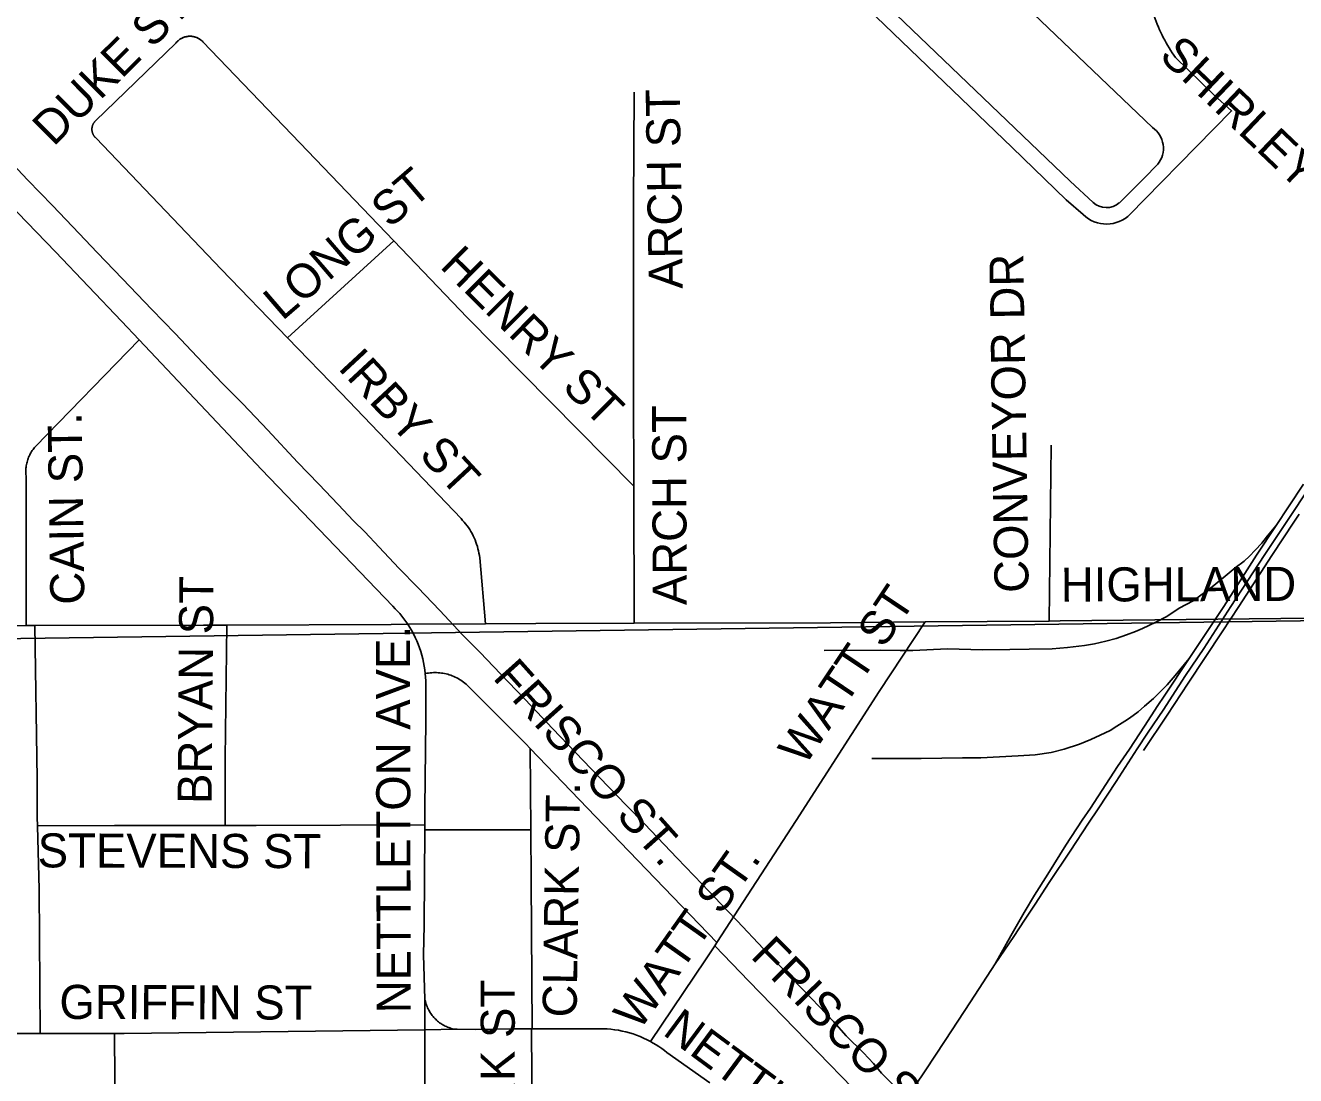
# Model space of a CAD drawing. Extents: x 1670563 to 1761545, y 515755 to 578944.
# Drawn here: x 1711003 to 1713800, y 543230 to 545541 of the extents above; entities that cross this region are included whole.
import ezdxf

# ---------------------------------------------------------------- set-up
doc = ezdxf.new("R2010")
doc.units = 0
for name, color, linetype in [('5_sectionlines', 7, 'Continuous'), ('AIRPORT', 7, 'Continuous'), ('RR Tracks', 7, 'Continuous'), ('STREETCL', 7, 'Continuous'), ('STRNAMES', 7, 'Continuous')]:
    doc.layers.add(name, color=color, linetype=linetype)

# ---------------------------------------------------------------- blocks, each defined once
blk = doc.blocks.new('RR TRACKS02')
at = {"layer": 'RR Tracks'}
for p, q in [((1710951.3, 545261.6), (1711008.8, 545200.8)), ((1711008.8, 545200.8), (1711062.7, 545145)), ((1711062.7, 545145), (1711121.5, 545083.4)), ((1711121.5, 545083.4), (1711161.2, 545041.8)), ((1711161.2, 545041.8), (1711216.9, 544983.9)), ((1711216.9, 544983.9), (1711281.6, 544916.4)), ((1711281.6, 544916.4), (1711332.7, 544863.4)), ((1711332.7, 544863.4), (1711381.4, 544811.8)), ((1711381.4, 544811.8), (1711436.9, 544753.8)), ((1711436.9, 544753.8), (1711482, 544708.1)), ((1711482, 544708.1), (1711537.4, 544650.1)), ((1711537.4, 544650.1), (1711602.6, 544579.8)), ((1711602.6, 544579.8), (1711649.4, 544531.7)), ((1713790.7, 544464.8), (1713852.9, 544558.2)), ((1711649.4, 544531.7), (1711692, 544486.9)), ((1713784.2, 544481.7), (1713817.6, 544531.4)), ((1711692, 544486.9), (1711725.8, 544451)), ((1713757, 544440.9), (1713784.2, 544481.7)), ((1711725.8, 544451), (1711750.4, 544426.4)), ((1713730.8, 544374.5), (1713790.7, 544464.8)), ((1713747.8, 544374.2), (1713797.7, 544450.3)), ((1713797.7, 544450.3), (1713807.7, 544465.7)), ((1711750.4, 544426.4), (1711782.1, 544392.5)), ((1713713.8, 544375.2), (1713757, 544440.9)), ((1713737.8, 544417.9), (1713725.9, 544401.5)), ((1713757, 544440.9), (1713737.8, 544417.9)), ((1711782.1, 544392.5), (1711825.6, 544346.5)), ((1713725.9, 544401.5), (1713711.1, 544386.1)), ((1713641.6, 544262.2), (1713713.8, 544375.2)), ((1713657.6, 544261.9), (1713730.8, 544374.5)), ((1713687, 544362.3), (1713667.1, 544347.2)), ((1713674.6, 544262.5), (1713747.8, 544374.2)), ((1713698.6, 544372.7), (1713687, 544362.3)), ((1713711.1, 544386.1), (1713698.6, 544372.7)), ((1711825.6, 544346.5), (1711867.6, 544304)), ((1713667.1, 544347.2), (1713644.9, 544328.8)), ((1713644.9, 544328.8), (1713616.2, 544305.2)), ((1711867.6, 544304), (1711915.9, 544253.6)), ((1713616.2, 544305.2), (1713574.3, 544274.7)), ((1711915.9, 544253.6), (1711966.7, 544199.1)), ((1713543.8, 544258.3), (1713516.5, 544239.9)), ((1713574.3, 544274.7), (1713543.8, 544258.3)), ((1713565.4, 544148), (1713641.6, 544262.2)), ((1713597.9, 544170.1), (1713657.6, 544261.9)), ((1713638.1, 544206.1), (1713674.6, 544262.5)), ((1713491.9, 544227.9), (1713462.9, 544214.1)), ((1713516.5, 544239.9), (1713491.9, 544227.9)), ((1711966.7, 544199.1), (1712004.7, 544160.7)), ((1713427.3, 544199.6), (1713404.6, 544191.7)), ((1713447.5, 544207.5), (1713427.3, 544199.6)), ((1713462.9, 544214.1), (1713447.5, 544207.5)), ((1713563.6, 544093.5), (1713638.1, 544206.1)), ((1712887, 544166.4), (1712761.8, 544165.1)), ((1712929.4, 544165.4), (1712887, 544166.4)), ((1713033.2, 544169.2), (1712957.1, 544165.1)), ((1713110.8, 544167), (1713033.2, 544169.2)), ((1713171, 544167.3), (1713110.8, 544167)), ((1713213.1, 544168), (1713171, 544167.3)), ((1713263.8, 544168.9), (1713213.1, 544168)), ((1713297.5, 544171.7), (1713263.8, 544168.9)), ((1713335.3, 544176.2), (1713297.5, 544171.7)), ((1713357.5, 544180), (1713335.3, 544176.2)), ((1713382.4, 544186), (1713357.5, 544180)), ((1713404.6, 544191.7), (1713382.4, 544186)), ((1713557.8, 544110.5), (1713597.9, 544170.1)), ((1712004.7, 544160.7), (1712034.3, 544129.8)), ((1712957.1, 544165.1), (1712929.4, 544165.4)), ((1713510.5, 544065), (1713565.4, 544148)), ((1713565.4, 544148), (1713534.5, 544110.2)), ((1712034.3, 544129.8), (1712117.4, 544043)), ((1713534.5, 544110.2), (1713516.9, 544089.7)), ((1713528.1, 544064.7), (1713557.8, 544110.5)), ((1713516.9, 544089.7), (1713499.9, 544072.4)), ((1713517.5, 544022.7), (1713563.6, 544093.5)), ((1713487, 544059.8), (1713467.4, 544042.5)), ((1713499.9, 544072.4), (1713487, 544059.8)), ((1713496.6, 544044.2), (1713510.5, 544065)), ((1713509.5, 544036.3), (1713528.1, 544064.7)), ((1712117.4, 544043), (1712164, 543993.8)), ((1713453.6, 544030.5), (1713434.3, 544016.7)), ((1713467.4, 544042.5), (1713453.6, 544030.5)), ((1713467.3, 543999.1), (1713496.6, 544044.2)), ((1713473.6, 543983.4), (1713509.5, 544036.3)), ((1713406.5, 543998.5), (1713391.4, 543989.4)), ((1713423.8, 544009.5), (1713406.5, 543998.5)), ((1713434.3, 544016.7), (1713423.8, 544009.5)), ((1713434.1, 543947.9), (1713467.3, 543999.1)), ((1713465.2, 543945.2), (1713517.5, 544022.7)), ((1712164, 543993.8), (1712248.7, 543905.1)), ((1713370, 543978.7), (1713349.3, 543969.1)), ((1713391.4, 543989.4), (1713370, 543978.7)), ((1713450.8, 543948.8), (1713473.6, 543983.4)), ((1713290.3, 543948), (1713261.7, 543941.1)), ((1713324.4, 543959.4), (1713290.3, 543948)), ((1713349.3, 543969.1), (1713324.4, 543959.4)), ((1713404.8, 543877.3), (1713450.8, 543948.8)), ((1713408, 543910.1), (1713434.1, 543947.9)), ((1712975.6, 543927.8), (1712867.2, 543927.5)), ((1713066.2, 543929.4), (1712975.6, 543927.8)), ((1713107, 543929.4), (1713066.2, 543929.4)), ((1713189.3, 543933.5), (1713107, 543929.4)), ((1713226.5, 543936), (1713189.3, 543933.5)), ((1713261.7, 543941.1), (1713226.5, 543936)), ((1712248.7, 543905.1), (1712326.4, 543824.5)), ((1713348.3, 543817.9), (1713408, 543910.1)), ((1713365.6, 543816.6), (1713404.8, 543877.3)), ((1712326.4, 543824.5), (1712366.5, 543783.6)), ((1713330, 543792.1), (1713348.3, 543817.9)), ((1713343.9, 543785.1), (1713365.6, 543816.6)), ((1712366.5, 543783.6), (1712438.2, 543708.3)), ((1713293.8, 543736.9), (1713330, 543792.1)), ((1713303.5, 543723.5), (1713343.9, 543785.1)), ((1713254.3, 543673), (1713293.8, 543736.9)), ((1713257.5, 543654.4), (1713303.5, 543723.5)), ((1712438.2, 543708.3), (1712493.1, 543650.6)), ((1713225.3, 543626.4), (1713254.3, 543673)), ((1712493.1, 543650.6), (1712548.1, 543593.3)), ((1713226.3, 543607.2), (1713257.5, 543654.4)), ((1713202.3, 543588.3), (1713225.3, 543626.4)), ((1713203, 543571.6), (1713226.3, 543607.2)), ((1712548.1, 543593.3), (1712570.2, 543570)), ((1713173.2, 543537), (1713202.3, 543588.3)), ((1712570.2, 543570), (1712628.2, 543508.9)), ((1713179.5, 543535.5), (1713203, 543571.6)), ((1713138.5, 543475.3), (1713173.2, 543537)), ((1713138.5, 543475.3), (1713179.5, 543535.5)), ((1712628.2, 543508.9), (1712680.7, 543454.5)), ((1713083.9, 543391.7), (1713138.5, 543475.3)), ((1712680.7, 543454.5), (1712719.2, 543414.5)), ((1712719.2, 543414.5), (1712750.1, 543382.1)), ((1713028.4, 543307.1), (1713083.9, 543391.7)), ((1712750.1, 543382.1), (1712783.3, 543347.6)), ((1712783.3, 543347.6), (1712810.5, 543317.3)), ((1712810.5, 543317.3), (1712848.4, 543279.5)), ((1712984.5, 543240.1), (1713028.4, 543307.1)), ((1712848.4, 543279.5), (1712870.4, 543255.8)), ((1712870.4, 543255.8), (1712888.1, 543235.1)), ((1712942.9, 543179.4), (1712888.1, 543235.1)), ((1712942.9, 543179.4), (1712984.5, 543240.1))]:
    blk.add_line(p, q, dxfattribs=at)

msp = doc.modelspace()

# ---------------------------------------------------------------- linework, layer by layer
at = {"layer": '5_sectionlines'}
msp.add_lwpolyline([(1685823.9, 543970.2), (1688486.3, 544044.1), (1693687.1, 544103.2), (1698961.5, 544118.1), (1704285.9, 544155), (1709574.3, 544171.9), (1714958.5, 544246.7), (1716656.1, 544265.6)], dxfattribs=at)
at = {"layer": 'AIRPORT'}
for points in [[(1713484.7, 545316.9), (1712615.7, 546147.6)], [(1713175.6, 545272.9), (1712427.2, 545992.9)], [(1712461.1, 546008.5), (1712520.8, 545949.4), (1713303.5, 545198.5), (1713354, 545151.7)], [(1713535.4, 545470.5), (1713619.8, 545388.8), (1713658.9, 545353.3), (1713581.8, 545274.8), (1713468.3, 545158.6), (1713436, 545126)], [(1713332.3, 545125.1), (1713294.9, 545157.7), (1713175.6, 545272.9)], [(1713411.9, 545151), (1713465.8, 545204.2), (1713496.4, 545235.8)]]:
    msp.add_lwpolyline(points, dxfattribs=at)
for centre, radius, start, end in [((1713825.7, 545676), 355.7, 198.6889, 215.2831), ((1713453.3, 545271), 55.6, 320.7847, 55.6675), ((1713383.3, 545183.4), 43.1, 227.2425, 311.4524), ((1713383.7, 545177.8), 73.6, 225.7198, 315.2283)]:
    msp.add_arc(centre, radius, start, end, dxfattribs=at)
at = {"layer": 'STREETCL'}
for points in [[(1711363.8, 545517.6), (1711362.4, 545517.5), (1711361.1, 545517.4), (1711359.7, 545517.2), (1711358.4, 545517), (1711357.1, 545516.7), (1711355.8, 545516.4), (1711354.5, 545516), (1711353.2, 545515.6), (1711352, 545515.2), (1711350.7, 545514.7), (1711349.5, 545514.1), (1711348.3, 545513.6), (1711347.1, 545512.9), (1711345.9, 545512.3), (1711344.7, 545511.6), (1711343.6, 545510.9), (1711342.5, 545510.1), (1711341.4, 545509.3), (1711340.4, 545508.4), (1711339.4, 545507.6), (1711338.4, 545506.6), (1711337.4, 545505.7), (1711336.5, 545504.7), (1711335.6, 545503.7), (1711334.8, 545502.7), (1711157.6, 545331.4), (1711156.9, 545330.8), (1711156.3, 545330.1), (1711155.7, 545329.4), (1711155.2, 545328.7), (1711154.6, 545328), (1711154.1, 545327.3), (1711153.6, 545326.5), (1711153.2, 545325.8), (1711152.7, 545325), (1711152.3, 545324.2), (1711152, 545323.4), (1711151.6, 545322.6), (1711151.3, 545321.7), (1711151, 545320.9), (1711150.7, 545320), (1711150.5, 545319.1), (1711150.3, 545318.3), (1711150.1, 545317.4), (1711150, 545316.5), (1711149.9, 545315.6), (1711149.8, 545314.7), (1711149.8, 545313.8), (1711149.8, 545312.9), (1711149.8, 545312)], [(1711814.8, 545067), (1711607.9, 545283), (1711394, 545505.5), (1711393.1, 545506.5), (1711392.1, 545507.4), (1711391.1, 545508.3), (1711390.1, 545509.1), (1711389, 545510), (1711387.9, 545510.7), (1711386.8, 545511.5), (1711385.6, 545512.2), (1711384.5, 545512.8), (1711383.3, 545513.5), (1711382.1, 545514), (1711380.8, 545514.6), (1711379.6, 545515.1), (1711378.3, 545515.5), (1711377, 545515.9), (1711375.7, 545516.3), (1711374.4, 545516.6), (1711373.1, 545516.9), (1711371.8, 545517.1), (1711370.5, 545517.3), (1711369.1, 545517.5), (1711367.8, 545517.6), (1711366.4, 545517.6), (1711365.1, 545517.6), (1711363.8, 545517.6)], [(1711254, 544849.1), (1711214.7, 544890.7), (1711069.5, 545042.7), (1710715.4, 545409.2), (1710644.5, 545483.7)], [(1712343.1, 544527), (1712342.5, 544735.3), (1712342.5, 545146.3), (1712344, 545394.6)], [(1711149.8, 545312), (1711149.8, 545311.1), (1711149.9, 545310.3), (1711150, 545309.4), (1711150.2, 545308.5), (1711150.4, 545307.6), (1711150.6, 545306.7), (1711150.8, 545305.9), (1711151.1, 545305), (1711151.4, 545304.2), (1711151.7, 545303.3), (1711152, 545302.5), (1711152.4, 545301.7), (1711152.8, 545300.9), (1711153.3, 545300.1), (1711153.7, 545299.4), (1711154.2, 545298.6), (1711154.7, 545297.9), (1711155.3, 545297.2), (1711155.8, 545296.5), (1711156.4, 545295.8), (1711157.1, 545295.2), (1711157.7, 545294.5), (1711158.3, 545293.9), (1711159, 545293.3), (1711434.4, 545005), (1711580.4, 544853.8)], [(1711580.4, 544853.8), (1711814.8, 545067)], [(1712343.1, 544527), (1711976.2, 544898.4), (1711814.8, 545067)], [(1711004.9, 544220.4), (1711004.9, 544549.8), (1711004.6, 544552.5), (1711004.4, 544555.3), (1711004.3, 544558.1), (1711004.3, 544560.9), (1711004.3, 544563.7), (1711004.5, 544566.5), (1711004.8, 544569.3), (1711005.2, 544572), (1711005.6, 544574.8), (1711006.2, 544577.5), (1711006.9, 544580.2), (1711007.6, 544582.9), (1711008.5, 544585.6), (1711009.4, 544588.2), (1711010.4, 544590.8), (1711011.5, 544593.4), (1711012.8, 544595.9), (1711014, 544598.4), (1711015.4, 544600.8), (1711016.9, 544603.2), (1711018.4, 544605.5), (1711020.1, 544607.8), (1711021.8, 544610), (1711023.5, 544612.1), (1711025.4, 544614.2), (1711254, 544849.1)], [(1711845.1, 544223.1), (1711841, 544229.2), (1711836.6, 544235.1), (1711832.1, 544240.9), (1711827.4, 544246.5), (1711822.5, 544252), (1711817.5, 544257.4), (1711812.3, 544262.6), (1711523.4, 544563.7), (1711254, 544849.1)], [(1711580.4, 544853.8), (1711698.3, 544731.7), (1711962.5, 544455.6), (1711966, 544451.9), (1711969.4, 544448), (1711972.6, 544444.1), (1711975.7, 544440), (1711978.7, 544435.8), (1711981.5, 544431.5), (1711984.2, 544427.2), (1711986.7, 544422.7), (1711989, 544418.1), (1711991.2, 544413.5), (1711993.3, 544408.8), (1711995.1, 544404.1), (1711996.8, 544399.2), (1711998.4, 544394.3), (1711999.8, 544389.4), (1712001, 544384.4), (1712002, 544379.4), (1712002.8, 544374.4), (1712003.5, 544369.3), (1712016.2, 544224.2)], [(1713257.7, 544230.1), (1713261.8, 544617.6)], [(1712344, 544225.4), (1712343.1, 544527)], [(1711845.1, 544223.1), (1711808.8, 544222.9), (1711446.5, 544221.3)], [(1712016.2, 544224.2), (1711845.1, 544223.1)], [(1711883.8, 544114.5), (1711882.9, 544122.7), (1711881.6, 544131), (1711880.1, 544139.1), (1711878.3, 544147.3), (1711876.2, 544155.3), (1711873.8, 544163.3), (1711871.1, 544171.2), (1711868.2, 544179), (1711865, 544186.6), (1711861.5, 544194.2), (1711857.8, 544201.7), (1711853.8, 544209), (1711849.6, 544216.1), (1711845.1, 544223.1)], [(1712344, 544225.4), (1712127, 544224.8), (1712016.2, 544224.2)], [(1712984.6, 544228.1), (1712775.9, 544226.6), (1712344, 544225.4)], [(1712525.6, 543522.2), (1712700.1, 543791.4), (1712882.9, 544075.3), (1712984.6, 544228.1)], [(1713257.7, 544230.1), (1712984.6, 544228.1)], [(1713983.6, 544237.9), (1713767.4, 544236), (1713281.6, 544230.3), (1713257.7, 544230.1)], [(1711004.9, 544220.4), (1710411, 544219.3), (1710173.8, 544217.4), (1710080.8, 544217.4)], [(1711024.4, 544220.4), (1711004.9, 544220.4)], [(1711446.5, 544221.3), (1711395.7, 544221.1), (1711024.4, 544220.4)], [(1711029.6, 543779.5), (1711029.1, 543797.6), (1711029.1, 543882.5), (1711024.4, 544220.4)], [(1711443.3, 543780.2), (1711443.3, 543927.9), (1711446.5, 544221.3)], [(1711882.5, 543781.6), (1711882.8, 543819.2), (1711885, 544010.2), (1711885, 544091), (1711884.9, 544098.8), (1711884.5, 544106.6), (1711883.8, 544114.5)], [(1712114.6, 543949.8), (1712105.2, 543959.7), (1711978.7, 544086.3), (1711976.1, 544088.8), (1711973.5, 544091.2), (1711970.8, 544093.5), (1711968, 544095.7), (1711965.1, 544097.8), (1711962.2, 544099.8), (1711959.2, 544101.7), (1711956.1, 544103.5), (1711953, 544105.1), (1711949.8, 544106.7), (1711946.5, 544108.2), (1711943.2, 544109.5), (1711939.9, 544110.8), (1711936.5, 544111.9), (1711933.1, 544112.9), (1711929.7, 544113.8), (1711926.2, 544114.6), (1711922.7, 544115.3), (1711919.2, 544115.8), (1711915.7, 544116.2), (1711912.1, 544116.5), (1711908.6, 544116.7), (1711905, 544116.7), (1711901.5, 544116.6), (1711897.9, 544116.4), (1711894.4, 544116.1), (1711890.8, 544115.7), (1711887.3, 544115.1), (1711883.8, 544114.5)], [(1712115.8, 543770.8), (1712114.6, 543949.8)], [(1712525.6, 543522.2), (1712312.8, 543743.7), (1712114.6, 543949.8)], [(1711029.6, 543779.5), (1711199.6, 543780.2), (1711443.3, 543780.2)], [(1711035.7, 543322.2), (1711033.3, 543639.4), (1711029.6, 543779.5)], [(1711443.3, 543780.2), (1711511.5, 543780.2), (1711882.5, 543781.6)], [(1711882.5, 543770.8), (1711882.5, 543781.6)], [(1711882.8, 543397.9), (1711879.6, 543495.2), (1711881.2, 543561), (1711882.5, 543770.8)], [(1711882.5, 543770.8), (1712115.8, 543770.8)], [(1712119, 543332.8), (1712116.6, 543658.7), (1712115.8, 543770.8)], [(1712379.4, 543304.7), (1712500.9, 543484.2), (1712521, 543515.1)], [(1712521, 543515.1), (1712525.6, 543522.2)], [(1712850.1, 543176.5), (1712595.8, 543437.5), (1712521, 543515.1)], [(1711882.8, 543329.9), (1711882.8, 543397.9)], [(1711953.8, 543331.9), (1711946.3, 543332), (1711943.5, 543332.7), (1711940.8, 543333.4), (1711938.1, 543334.3), (1711935.4, 543335.2), (1711932.7, 543336.3), (1711930.1, 543337.4), (1711927.5, 543338.6), (1711925, 543339.9), (1711922.5, 543341.3), (1711920.1, 543342.8), (1711917.7, 543344.4), (1711915.4, 543346), (1711913.1, 543347.7), (1711910.9, 543349.5), (1711908.7, 543351.4), (1711906.7, 543353.4), (1711904.6, 543355.4), (1711902.7, 543357.5), (1711900.8, 543359.6), (1711899, 543361.8), (1711897.3, 543364.1), (1711895.7, 543366.4), (1711894.1, 543368.8), (1711892.7, 543371.3), (1711891.3, 543373.8), (1711890, 543376.3), (1711888.8, 543378.9), (1711887.6, 543381.5), (1711886.6, 543384.2), (1711885.7, 543386.9), (1711884.8, 543389.6), (1711884.1, 543392.3), (1711883.4, 543395.1), (1711882.8, 543397.9)], [(1711199.4, 543322.2), (1711220.7, 543322.2), (1711882.8, 543329.9)], [(1711881.8, 543125.7), (1711882.8, 543213.9), (1711882.8, 543329.9)], [(1711882.8, 543329.9), (1711953.8, 543331.9)], [(1712117.5, 543332.8), (1712074.9, 543332.8), (1711993.9, 543331.2), (1711953.8, 543331.9)], [(1712119.3, 543124.6), (1712117.5, 543332.8)], [(1712379.4, 543304.7), (1712372, 543308.5), (1712364.4, 543312.1), (1712356.8, 543315.3), (1712349, 543318.4), (1712341.1, 543321.1), (1712333.1, 543323.6), (1712325.1, 543325.7), (1712317, 543327.6), (1712308.8, 543329.2), (1712300.6, 543330.6), (1712292.3, 543331.6), (1712284, 543332.3), (1712275.7, 543332.8), (1712117.5, 543332.8)], [(1710596.4, 543322.2), (1711035.7, 543322.2)], [(1711035.7, 543322.2), (1711199.4, 543322.2)], [(1711199.4, 543322.2), (1711201, 543120.6)], [(1712510, 543213.4), (1712415.9, 543280.5), (1712410.2, 543285), (1712404.3, 543289.3), (1712398.2, 543293.4), (1712392.1, 543297.4), (1712385.8, 543301.1), (1712379.4, 543304.7)]]:
    msp.add_lwpolyline(points, dxfattribs=at)

# ---------------------------------------------------------------- block references
msp.add_blockref('RR TRACKS02', (0, 0), dxfattribs=at)

# ---------------------------------------------------------------- texts
at = {"layer": 'STRNAMES'}
for s, rotation, p in [('DUKE ST', 44.7988, (1711064.9, 545273.2)), ('SHIRLEY ANN DR', 316.4058, (1713497, 545471.2)), ('ARCH ST', 90.9047, (1712450.8, 544961.9)), ('LONG ST', 40.6893, (1711568.9, 544889.7)), ('HENRY ST', 315.2626, (1711913.5, 545009.6)), ('CONVEYOR DR', 90.9034, (1713212.3, 544292.8)), ('IRBY ST', 312.8668, (1711689.3, 544786.5)), ('ARCH ST', 90.1811, (1712459.5, 544265.2)), ('CAIN ST.', 90.8499, (1711133.4, 544266.6)), ('HIGHLAND DR (HWY 18)', 0.1751, (1713283.1, 544273)), ('BRYAN ST', 89.5269, (1711413.3, 543827.3)), ('WATT ST', 56.159, (1712719, 543908.7)), ('NETTLETON AVE.', 90.118, (1711851.8, 543366.9)), ('FRISCO ST.', 311.841, (1712030.4, 544104.4)), ('CLARK ST.', 89.118, (1712216.8, 543357.1)), ('STEVENS ST', 359.8249, (1711030.3, 543687.9)), ('WATT ST.', 54.6844, (1712354.9, 543326.1)), ('FRISCO ST.', 314.3467, (1712597.6, 543490.7)), ('GRIFFIN ST', 359.8259, (1711078.1, 543354.3)), ('CLARK ST', 89.9651, (1712080.5, 542950)), ('NETTLETON', 323.4641, (1712404, 543321.3))]:
    msp.add_text(s, height=75, rotation=rotation, dxfattribs=at).set_placement(p)

doc.saveas('drawing.dxf')
